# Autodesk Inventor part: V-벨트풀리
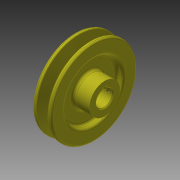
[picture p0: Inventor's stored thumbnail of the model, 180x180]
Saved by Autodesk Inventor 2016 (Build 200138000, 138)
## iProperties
Created: 2015-09
Part Number: V-벨트풀리
Material: 강철, 연강
Document SubType Name: Modeling
Designer: mduedu
Density: 7.86 g/cm^3
Mass: 779.014 g
Surface Area: 277.465 cm^2
Volume: 99.1112 cm^3
Appearance: 강철
Author: mduedu
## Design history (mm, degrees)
sketch "스케치1"
  geometry: L1 (-10, 0)-(10, 0); L2 (-10, 0)-(-10, 45); L3 (-10, 45)-(-5.976, 45); L4 (-5.976, 45)-(-2.154, 32.5); L5 (-2.154, 32.5)-(2.154, 32.5); L6 (2.154, 32.5)-(5.976, 45); L7 (5.976, 45)-(10, 45); L8 (10, 45)-(10, 0); L9 (0, 0)-(0, 32.5); L10 (-10, 40.5)-(10, 40.5); 3 further points
  constraints: 20 end point, 6 point on line, 3 perpendicular, 2 midpoint, 2 parallel, 2 symmetric about line, 1 coincident, 1 collinear, 1 equal length, 1 horizontal, 1 vertical, 1 vertical alignment
  dimensions: "d0" = 20 distance between parallel lines of L8 L2; "d2" = 90 diameter of L3 L1; "d5" = 8 distance between parallel lines of L5 L10; "d6" = 9.2 distance of point (4.6, 40.5) point (-4.6, 40.5); "d7" = 34 deg angle of L6 L4; "d40" = 4.5 distance between parallel lines of L3 L10
revolve "회전1" sketch "스케치1" stored, may be unused: angle "d8" = 90 deg
sketch "스케치2"
  geometry: C1 r 16 at (0, 0); 1 further point
  constraints: 1 centre point, 1 coincident
  dimensions: "d9" = 32 diameter of C1
extrude "돌출1" join sketch "스케치2" distance "d10" = 11; taper "d11" = 0 deg
fillet "모깎기1" dims "d12" = 1, "d13" = 0.5, "d14" = 2
sketch "스케치3"
  geometry: C1 r 16 at (0, 0) reference; C2 r 30 at (0, 0); 1 further point
  constraints: 1 centre point, 1 coincident
  dimensions: "d15" = 60 diameter of C2
extrude "돌출2" cut sketch "스케치3" distance "d16" = 6; taper "d17" = 0 deg
fillet "모깎기2" dims "d18" = 3
fillet "모깎기3" dims "d19" = 3
fillet "모깎기4" dims "d20" = 3
sketch "스케치4"
  geometry: C1 r 8.5 at (0, 0); 1 further point
  constraints: 1 centre point, 1 coincident
  dimensions: "d21" = 17 diameter of C1
extrude "돌출3" cut sketch "스케치4" stored distance "d22" = 4; taper "d23" = 0 deg
sketch "스케치5"
  geometry: L1 (-2.5, 8.124)-(2.5, 8.124); L2 (2.5, 8.124)-(2.5, 10.8); L3 (2.5, 10.8)-(-2.5, 10.8); L4 (-2.5, 10.8)-(-2.5, 8.124); A1 r 8.5 centre (0, 0) between (-2.5, 8.124) and (2.5, 8.124) reference; 2 further points
  constraints: 8 end point, 3 point on circle, 2 parallel, 1 horizontal, 1 perpendicular, 1 vertical alignment
  dimensions: "d24" = 5 distance of L2.end L3.end; "d26" = 19.3 distance from line of L3 point (0, -8.5)
extrude "돌출4" cut sketch "스케치5" stored distance "d27" = 4; taper "d28" = 0 deg
chamfer "모따기1" distance "d29" = 1; stored, may be unused: second distance "d30" = 2, angle "d31" = 45 deg
node "작업 평면1"
sketch "스케치6"
  geometry: L1 (-11, 16)-(-11, -16) reference; 2 further points
  constraints: 1 horizontal alignment
  dimensions: "d32" = 5 distance from line of point (-6, 0) L1
hole "구멍1" sketch "스케치6" at (-6, 0) diameter "d33" = 3.242; stored, may be unused: countersink angle "d37" = 90 deg, drill point angle "d39" = 118 deg; dims "d34" = 6, "d35" = 4, "d36" = 2, "d38" = 8
node "솔리드1"
mirror "대칭1"
